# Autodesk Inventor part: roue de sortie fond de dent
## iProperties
Shininess: 64.0
Length Units: 11269
Angle Units: 11279
Time Units: 11290
Mass Units: 11283
Length Display Precision: 3
Angle Display Precision: 2
Compacted: True
Part Number: roue de sortie fond de dent
Document SubType Name: Modeling
Created: 2004-09
Material: Par défaut
Designer: Administrateur
Density: 1 g/cm^3
Density: 0.0
Volumn: 0.0
Area: 0.0
PropertySet Name: Model Information
Control State: 0
Master: False
Checked Out: False
Author: Administrateur
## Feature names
1. Extrusion1
